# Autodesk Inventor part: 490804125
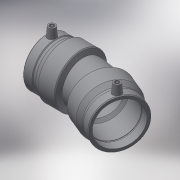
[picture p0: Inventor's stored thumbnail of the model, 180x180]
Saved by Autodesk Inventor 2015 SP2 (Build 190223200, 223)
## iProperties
Created: 2017-06
Part Number: 490804125
Material: Generic
Description: PLASSON 22.5° ELBOW 125
Document SubType Name: Modeling
Designer: KIM
Mass: 55.0731 g
Surface Area: 148.067 cm^2
Volume: 55.0731 cm^3
Density: 1 g/cm^3
Appearance: Default
Author: KIM
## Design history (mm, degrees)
derived "490804.ipt"
feature "Solid1::490804.ipt"
tag "TaggingFeature1"
body "Solid1"
other parameters: "d14" = 17.6296, "d18" = 125, "d19" = 3.52592, "d20" = 168 deg, "d22" = 151.8, "d23" = 165, "d24" = 147.246, "d29" = 88, "d35" = 15, "d39" = 5 deg, "d45" = 4, "d46" = 14, "d47" = 0, "d65" = 125, "d67" = 45 deg, "d71" = 157.5 deg, "d75" = 8.25, "d82" = 45 deg, "d83" = 86, "d84" = 148.5, "d94" = 157.5 deg, "d95" = 73.623, "d98" = 274, "d99" = 82.2, "d105" = 24.94, "d106" = 6.235, "d_" = 125, "L_" = 274, "L_1" = 86, "D_" = 165, "A_" = 88, "d_2" = 12
